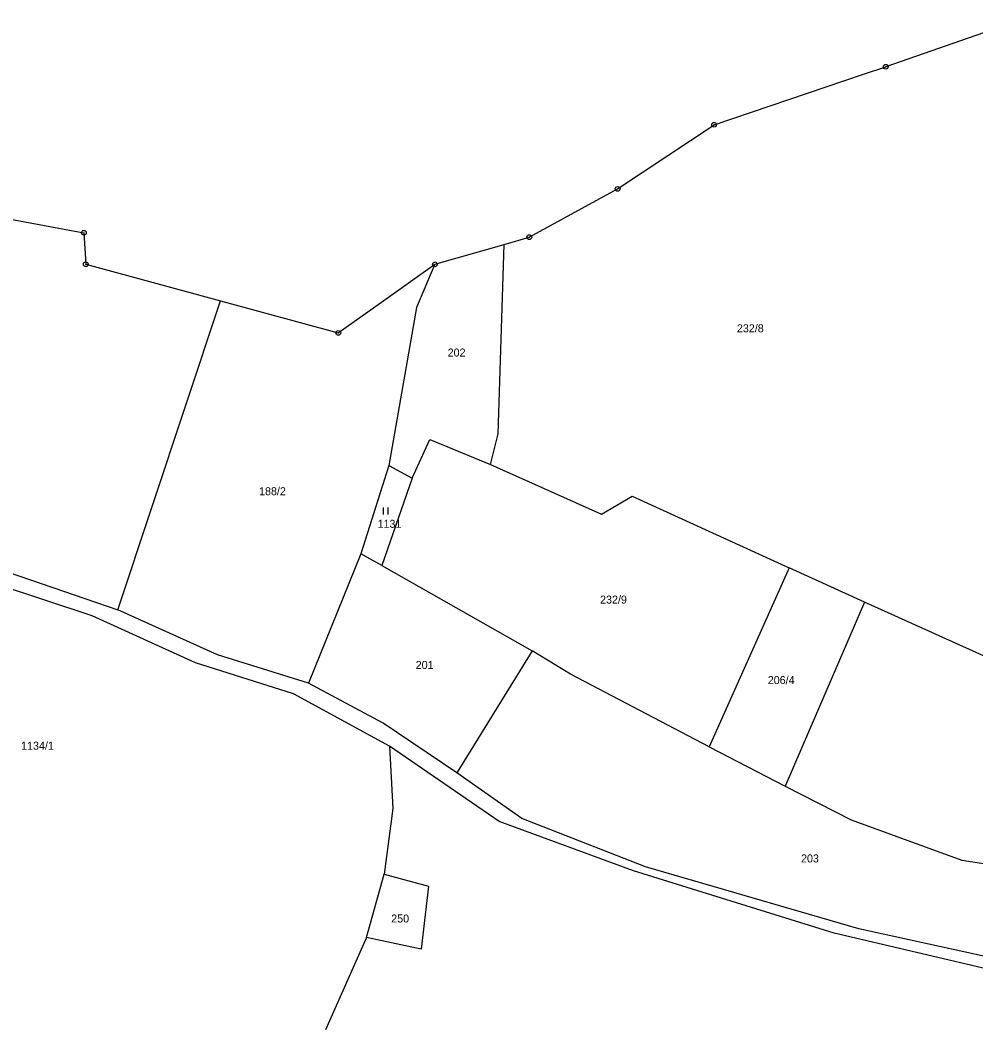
# Model space of a CAD drawing. Extents: x -765428 to -762163, y -1107632 to -1104975.
# Drawn here: x -762948.5 to -762745.6, y -1106134.4 to -1105920.1 of the extents above; entities that cross this region are included whole.
import ezdxf
from ezdxf.enums import TextEntityAlignment as Align

# ---------------------------------------------------------------- set-up
doc = ezdxf.new("R2010")
doc.units = 0
doc.header["$LTSCALE"] = 0.68
for name, color, linetype, lineweight in [('1', 7, 'Continuous', 25), ('3', 7, 'Continuous', 25), ('8', 7, 'Continuous', 25)]:
    doc.layers.add(name, color=color, linetype=linetype, lineweight=lineweight)
doc.layers.add('2', color=7, linetype='Continuous')

msp = doc.modelspace()

# ---------------------------------------------------------------- linework, layer by layer
at = {"layer": '1'}
for p, q in [((-762736.18, -1105920.15), (-762764.73, -1105930.04)), ((-762769.49, -1105931.65), (-762764.73, -1105930.04)), ((-762801.16, -1105942.35), (-762769.49, -1105931.65)), ((-762821.64, -1105955.98), (-762801.16, -1105942.35)), ((-762840.39, -1105966.24), (-762821.64, -1105955.98)), ((-762951.64, -1105962.22), (-762934.94, -1105965.31)), ((-762934.94, -1105965.31), (-762934.53, -1105971.98)), ((-762845.71, -1105967.77), (-762840.39, -1105966.24)), ((-762860.42, -1105972.01), (-762845.71, -1105967.77)), ((-762847.01, -1106008), (-762845.71, -1105967.77)), ((-762934.53, -1105971.98), (-762905.92, -1105979.78)), ((-762871.27, -1105979.72), (-762860.42, -1105972.01)), ((-762860.42, -1105972.01), (-762864.34, -1105981.15)), ((-762880.93, -1105986.59), (-762871.27, -1105979.72)), ((-762927.7, -1106045.36), (-762905.92, -1105979.78)), ((-762905.92, -1105979.78), (-762880.93, -1105986.59)), ((-762864.34, -1105981.15), (-762870.23, -1106014.74)), ((-762865.28, -1106017.43), (-762861.51, -1106009.25)), ((-762861.51, -1106009.25), (-762848.64, -1106014.53)), ((-762848.64, -1106014.53), (-762847.01, -1106008)), ((-762870.23, -1106014.74), (-762876.12, -1106033.5)), ((-762870.23, -1106014.74), (-762865.28, -1106017.43)), ((-762848.64, -1106014.53), (-762825.05, -1106025.04)), ((-762865.28, -1106017.43), (-762871.7, -1106035.95)), ((-762825.05, -1106025.04), (-762818.56, -1106021.24)), ((-762818.56, -1106021.24), (-762785.26, -1106036.5)), ((-762933.2, -1106046.65), (-762975.94, -1106032.52)), ((-762967.58, -1106031.73), (-762927.7, -1106045.36)), ((-762876.12, -1106033.5), (-762887.23, -1106060.95)), ((-762871.7, -1106035.95), (-762876.12, -1106033.5)), ((-762871.7, -1106035.95), (-762839.77, -1106054.13)), ((-762785.26, -1106036.5), (-762802.25, -1106074.51)), ((-762769.22, -1106043.75), (-762785.26, -1106036.5)), ((-762743.34, -1106055.44), (-762769.22, -1106043.75)), ((-762906.54, -1106054.94), (-762927.7, -1106045.36)), ((-762911.24, -1106056.62), (-762933.2, -1106046.65)), ((-762839.77, -1106054.13), (-762855.75, -1106079.99)), ((-762831.66, -1106059.03), (-762839.77, -1106054.13)), ((-762890.47, -1106063.23), (-762911.24, -1106056.62)), ((-762887.23, -1106060.95), (-762906.54, -1106054.94)), ((-762871.38, -1106069.46), (-762887.23, -1106060.95)), ((-762802.25, -1106074.51), (-762831.66, -1106059.03)), ((-762870.1, -1106074.34), (-762890.47, -1106063.23)), ((-762855.75, -1106079.99), (-762871.38, -1106069.46)), ((-762846.78, -1106090.38), (-762870.1, -1106074.34)), ((-762870.1, -1106074.34), (-762869.36, -1106087.59)), ((-762802.25, -1106074.51), (-762786.08, -1106082.82)), ((-762841.95, -1106089.7), (-762855.75, -1106079.99)), ((-762869.36, -1106087.59), (-762871.19, -1106101.53)), ((-762818.3, -1106100.82), (-762846.78, -1106090.38)), ((-762815.7, -1106099.95), (-762841.95, -1106089.7)), ((-762772.1, -1106090), (-762748.57, -1106098.55)), ((-762748.57, -1106098.55), (-762688.52, -1106108.04)), ((-762874.94, -1106114.98), (-762871.19, -1106101.53)), ((-762871.19, -1106101.53), (-762861.78, -1106104.07)), ((-762775.71, -1106114.08), (-762818.3, -1106100.82)), ((-762770.42, -1106113.12), (-762815.7, -1106099.95)), ((-762861.78, -1106104.07), (-762863.35, -1106117.48)), ((-762718.45, -1106127.47), (-762775.71, -1106114.08)), ((-762719.27, -1106124.46), (-762770.42, -1106113.12)), ((-762874.94, -1106114.98), (-762883.63, -1106134.57)), ((-762863.35, -1106117.48), (-762874.94, -1106114.98))]:
    msp.add_line(p, q, dxfattribs=at)
msp.add_lwpolyline([(-762769.22, -1106043.75), (-762786.08, -1106082.82), (-762772.1, -1106090)], dxfattribs=at)
at = {"layer": '3'}
for p, q in [((-762871.331, -1106025.17), (-762871.331, -1106023.67)), ((-762870.33, -1106025.17), (-762870.33, -1106023.67))]:
    msp.add_line(p, q, dxfattribs=at)
at = {"layer": '8'}
for centre, radius in [((-762764.73, -1105930.0399), 0.5), ((-762764.73, -1105930.0399), 0.0303), ((-762801.16, -1105942.3499), 0.5), ((-762801.16, -1105942.3499), 0.0303), ((-762821.64, -1105955.9799), 0.5), ((-762821.64, -1105955.9799), 0.0303), ((-762934.94, -1105965.3099), 0.5), ((-762934.94, -1105965.3099), 0.0303), ((-762840.39, -1105966.2399), 0.5), ((-762840.39, -1105966.2399), 0.0303), ((-762934.53, -1105971.9799), 0.5), ((-762934.53, -1105971.9799), 0.0303), ((-762860.42, -1105972.0099), 0.5), ((-762860.42, -1105972.0099), 0.0303), ((-762880.93, -1105986.5899), 0.5), ((-762880.93, -1105986.5899), 0.0303)]:
    msp.add_circle(centre, radius, dxfattribs=at)

# ---------------------------------------------------------------- texts
at = {"layer": '2'}
for s, p in [('232/8', (-762793.48, -1105986.445)), ('232/9', (-762822.52, -1106044.065)), ('206/4', (-762786.93, -1106061.165)), ('203', (-762780.819, -1106099.045))]:
    msp.add_text(s, height=1.7, dxfattribs=at).set_placement(p, align=Align.CENTER)
for s, p in [('202', (-762857.72, -1105991.595)), ('188/2', (-762897.75, -1106021.055)), ('1131', (-762872.6, -1106027.975)), ('201', (-762864.5, -1106057.955)), ('1134/1', (-762948.26, -1106075.105)), ('250', (-762869.7, -1106111.805))]:
    msp.add_text(s, height=1.7, dxfattribs=at).set_placement(p)

doc.saveas('drawing.dxf')
